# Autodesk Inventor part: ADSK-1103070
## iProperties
Shininess: 50.0
Length Units: 11272
Angle Units: 11279
Time Units: 11290
Mass Units: 11286
Length Display Precision: 4
Angle Display Precision: 2
Compacted: True
Created: 2000-08
Part Number: ADSK-1103070
Document SubType Name: Modeling
Description: MUFFLER
Mass: 6.22905 g
Surface Area: 202.15 cm^2
Volume: 6.22905 cm^3
Density: 1 g/cm^3
Density: 0.0
Volumn: 0.0
Area: 0.0
PropertySet Name: Model Information
Control State: 0
Master: False
Checked Out: False
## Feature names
1. Fillet14
